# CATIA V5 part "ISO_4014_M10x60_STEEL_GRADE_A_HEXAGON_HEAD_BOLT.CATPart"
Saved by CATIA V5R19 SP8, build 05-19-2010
Part number: ISO 4014 BOLT M10x60 STEEL GRADE A HEXAGON HEAD
Nomenclature: 28
Publications: "Mating Face", "Axis"
Bounding box of the stored display mesh (mm): x -60 to 6.58, y -8 to 8, z -9.238 to 9.238
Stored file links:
  C:\Users\rphgr\Desktop\0_Tapis_TC520B_vitesse\ISO_4014_M10x60_STEEL_GRADE_A_HEXAGON_HEAD_BOLT.CATPart
  D:\Programmes\DassaultSysteme\win_b64\startup\components\MechanicalStandardParts\EN_Standards\Design_Tables\EN_ISO_4014_GRADES_A_B_HEXAGON_HEAD_BOLT.txt
  C:\Program Files\Dassault Systemes\B19\win_b64\startup\components\MechanicalStandardParts\ISO_Standards\Design_Tables\ISO_4014_GRADES_A_B_HEXAGON_HEAD_BOLT.txt
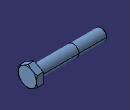
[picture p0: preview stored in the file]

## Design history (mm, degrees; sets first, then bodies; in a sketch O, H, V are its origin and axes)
Parameters
  d_dia = 10 mm
  l_length = 60 mm
  s_nom_across_flats = 16 mm
  k_max_head_depth = 6.58 mm
  dw_min = 14.63 mm
  r_min = 0.4 mm
  c_max = 0.6 mm
  p_pitch = 1.5 mm
  threading = 26 mm
Body1 "PartBody" (main body)
  Sketch1 on yz-plane, origin (0, 0, 0), H (0, 1, 0), V (0, 0, 1)
    circle A1 centre (0, 0) radius 7.315
    radius A1 = 7.315 {= dw_min /2}
  Pad1: profile Sketch1, direction (1, 0, 0), length 0.6 {= c_max}
  Sketch2 on face of Pad1, origin (0.6, 0, 0), H (0, 1, 0), V (0, 0, 1)
    point P1 (8, -4.6188)
    point P2 (8, 4.6188)
    point P3 (0, 9.2376)
    point P4 (-8, 4.6188)
    point P5 (-8, -4.6188)
    point P6 (0, -9.2376)
    point P7 (8, 0)
    line L1 (8, -4.6188) -> (8, 4.6188)
    line L2 (8, 4.6188) -> (0, 9.2376)
    line L3 (0, 9.2376) -> (-8, 4.6188)
    line L4 (-8, 4.6188) -> (-8, -4.6188)
    line L5 (-8, -4.6188) -> (0, -9.2376)
    line L6 (0, -9.2376) -> (8, -4.6188)
    construction line L7 (0, 0) -> (8, 0)
    construction circle A1 centre (0, 0) radius 9.2376
    construction arc A2 centre (-8, -4.6188) radius 9.2376 from (-8, 4.6188) to (0, -9.2376) cw
    construction arc A3 centre (8, 4.6188) radius 9.2376 from (0, 9.2376) to (8, -4.6188) ccw
    point P8 (-8, -4.6188)
    point P9 (8, 4.6188)
    distance L1 L4 = 16 {= s_nom_across_flats}
    horizontal: L7 H
    coincidence: A1 P1, A1 P2, A1 P3, A1 P4, A1 P5, A1 P6, A2 P4, A2 P6, A2 O, P8 P5, A3 P3, A3 P1, A3 O, P9 P2
    midpoint: P7 L1
  Pad2: profile Sketch2, direction (1, 0, 0), length 5.98 {= k_max_head_depth -c_max}
  Sketch3 on zx-plane, origin (0, 0, 0), H (-1, 0, 0), V (0, 0, 1)
    point P1 (-6.58, 7.9642)
    axis line L1 (-94.6904, 0) -> (76.7146, 0)
    reference intersected line E1 through (1000000, 0) direction (-1, 0) from xy-plane
    line L2 (-5.8448, 9.2376) -> (-6.58, 7.9642)
    line L3 (-5.8448, 9.2376) -> (-6.58, 9.2376)
    line L4 (-6.58, 9.2376) -> (-6.58, 7.9642)
    reference projected line E2 (-0.8, 9.2376) -> (-18.28, 9.2376) from edge [face of Pad2 | face of Pad2]
    distance P1 H = 7.9642 {= s_nom_across_flats /2.009}
    distance P1 V = 6.58 {= k_max_head_depth}
    angle L4 L2 = 30
    horizontal: L1 H, L3 H
    coincidence: L1 E1, L3 E2
    vertical: L4 V
  Groove1: profile Sketch3, axis Sketch3.L1, angle 360
  Sketch4 on face of Pad1, origin (0, 0, 0), H (0, -1, 0), V (0, 0, 1)
    circle A1 centre (0, 0) radius 5
    radius A1 = 5 {= d_dia /2}
  Pad3: profile Sketch4, direction (-1, 0, 0), length 34 {= l_length -threading}
  Sketch5 on face of Pad3, origin (-34, 0, 0), H (0, -1, 0), V (0, 0, 1)
    circle A1 centre (0, 0) radius 4.878
    radius A1 = 4.878 {= d_dia /2.05}
  Pad4: profile Sketch5, direction (-1, 0, 0), length 26 {= threading}
  Chamfer1: length 1.5 {= p_pitch}, angle 45, on face of Pad4
  Fillet1: radius 0.4 {= r_min}, on edge [face of Pad3 | face of Pad1]
  Thread1: diameter 9.7561 {= d_dia /1.025}, depth 26 {= threading}, pitch 1, on face of Pad4, from face of Pad4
